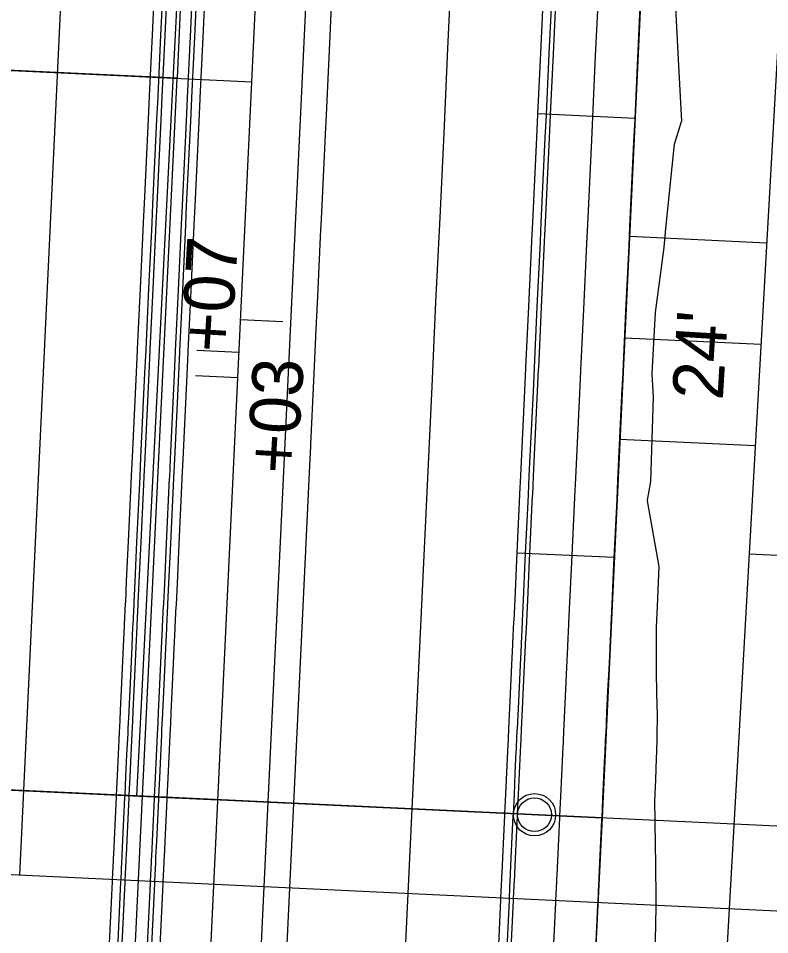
# Model space of a CAD drawing. Extents: x -70 to 701944, y -4 to 666871.
# Drawn here: x 668271.1 to 668360, y 655078.2 to 655186.6 of the extents above; entities that cross this region are included whole.
import ezdxf

# ---------------------------------------------------------------- set-up
doc = ezdxf.new("R2010")
doc.units = 0
for name, color, linetype in [('R_Detour', 7, 'Continuous'), ('R_Drive', 7, 'Continuous'), ('R_Horz Alg', 7, 'Continuous'), ('R_No Plot', 7, 'Continuous'), ('R_Proposed Const Limits', 7, 'Continuous'), ('R_Proposed Road', 7, 'Continuous'), ('R_ROW', 7, 'Continuous'), ('R_ROW Annot', 7, 'Continuous'), ('R_Striping', 7, 'Continuous'), ('R_Water', 7, 'Continuous'), ('T_Indications', 7, 'Continuous')]:
    doc.layers.add(name, color=color, linetype=linetype)

msp = doc.modelspace()

# ---------------------------------------------------------------- linework, layer by layer
at = {"layer": 'R_Detour'}
for p, q in [((668169.67, 655185.14), (668298.7, 655179.05)), ((668151.5, 655100.91), (668294.69, 655094.15)), ((668441.28, 655087.23), (668294.69, 655094.15))]:
    msp.add_line(p, q, dxfattribs=at)
at = {"layer": 'R_Drive'}
for p, q in [((668332.56, 655175.3), (668344.05, 655174.76)), ((668343.39, 655160.78), (668359.61, 655160.01)), ((668297.37, 655150.94), (668302.37, 655150.7)), ((668297.19, 655147.03), (668292.2, 655147.26)), ((668342.26, 655136.8), (668358.27, 655136.05)), ((668330.11, 655123.36), (668341.6, 655122.82))]:
    msp.add_line(p, q, dxfattribs=at)
at = {"layer": 'R_Horz Alg'}
msp.add_line((668254.91, 654251.16), (668327.61, 655791.56), dxfattribs=at)
msp.add_lwpolyline([(668292.06, 655144.33), (668297.05, 655144.09)], dxfattribs=at)
at = {"layer": 'R_No Plot'}
for p, q in [((668342.83, 655148.79), (668358.94, 655148.03)), ((668187.73, 655089.19), (668380.3, 655080.1))]:
    msp.add_line(p, q, dxfattribs=at)
for points in [[(668210.91, 655248.27), (668292.71, 655244.41), (668289.88, 655179.47), (668211.95, 655183.15)], [(668292.71, 655244.41), (668347.22, 655241.84), (668340.15, 655092), (668285.12, 655094.6)], [(668289.88, 655179.47), (668211.95, 655183.15), (668212.78, 655131.9), (668213.03, 655119.43), (668213.82, 655104.92), (668215.37, 655097.89), (668285.78, 655094.57)], [(668285.78, 655094.57), (668215.37, 655097.89), (668216.15, 655093.84), (668225.15, 655058.76), (668230.84, 655034.55), (668233.09, 655014.27), (668233.65, 654985.81), (668233.98, 654965.53), (668233.02, 654946.89), (668287.62, 654944.31), (668288.46, 654962.05), (668284.23, 655062.51)], [(668285.78, 655094.57), (668340.15, 655092), (668338.43, 655057.09), (668331.32, 654965.1), (668330.89, 654959.61), (668330.08, 654942.31), (668287.62, 654944.31), (668288.43, 654961.32), (668284.23, 655062.51)]]:
    msp.add_lwpolyline(points, close=True, dxfattribs=at)
msp.add_circle((668332.16, 655092.38), 2.5, dxfattribs=at)
at = {"layer": 'R_Proposed Const Limits'}
msp.add_lwpolyline([(668346.37, 655071.69), (668346.57, 655081.45), (668346.57, 655081.69), (668346.54, 655083.94), (668346.54, 655084.26), (668346.53, 655084.63), (668346.51, 655086.44), (668346.47, 655088.95), (668346.44, 655091.47), (668346.44, 655091.71), (668346.41, 655093.99), (668346.52, 655096.52), (668346.6, 655099.06), (668346.6, 655099.27), (668346.62, 655099.64), (668346.68, 655101.61), (668346.68, 655101.71), (668346.69, 655104.17), (668346.63, 655106.73), (668346.58, 655109.31), (668346.59, 655111.72), (668346.59, 655111.88), (668346.6, 655114.38), (668346.6, 655114.46), (668346.6, 655114.55), (668346.69, 655117.03), (668346.91, 655121.72), (668345.51, 655129.5), (668345.53, 655129.57), (668345.93, 655131.77), (668346.22, 655141.77), (668346.09, 655144.48), (668346.08, 655144.56), (668346.49, 655151.77), (668347.5, 655159.44), (668347.5, 655159.5), (668347.68, 655161.72), (668348.71, 655171.69), (668349.56, 655174.37), (668349.57, 655174.41), (668349.21, 655181.68), (668348.79, 655189.43)], dxfattribs=at)
at = {"layer": 'R_Proposed Road'}
for points in [[(668281.77, 655074.74), (668282.23, 655084.49), (668282.24, 655084.72), (668282.34, 655086.97), (668282.36, 655087.29), (668282.38, 655087.66), (668282.46, 655089.46), (668282.58, 655091.96), (668282.7, 655094.47), (668282.71, 655094.71), (668282.82, 655097), (668282.94, 655099.53), (668283.06, 655102.06), (668283.07, 655102.27), (668283.08, 655102.64), (668283.18, 655104.61), (668283.18, 655104.7), (668283.3, 655107.16), (668283.42, 655109.72), (668283.54, 655112.28), (668283.65, 655114.69), (668283.66, 655114.85), (668283.78, 655117.35), (668283.78, 655117.42), (668283.79, 655117.52), (668283.9, 655120), (668284.12, 655124.68), (668284.49, 655132.38), (668284.49, 655132.45), (668284.6, 655134.67), (668285.07, 655144.66), (668285.19, 655147.36), (668285.2, 655147.43), (668285.54, 655154.65), (668285.9, 655162.35), (668285.9, 655162.4), (668286.01, 655164.64), (668286.48, 655174.62), (668286.61, 655177.34), (668286.61, 655177.38), (668286.95, 655184.61), (668287.32, 655192.33)], [(668282.77, 655074.69), (668283.23, 655084.44), (668283.24, 655084.68), (668283.34, 655086.92), (668283.36, 655087.24), (668283.38, 655087.61), (668283.46, 655089.41), (668283.58, 655091.91), (668283.7, 655094.43), (668283.71, 655094.67), (668283.82, 655096.95), (668283.94, 655099.48), (668284.06, 655102.02), (668284.07, 655102.22), (668284.08, 655102.59), (668284.18, 655104.56), (668284.18, 655104.66), (668284.3, 655107.11), (668284.42, 655109.67), (668284.54, 655112.23), (668284.65, 655114.64), (668284.66, 655114.8), (668284.78, 655117.3), (668284.78, 655117.37), (668284.79, 655117.47), (668284.9, 655119.95), (668285.12, 655124.63), (668285.49, 655132.33), (668285.49, 655132.4), (668285.59, 655134.62), (668286.07, 655144.61), (668286.19, 655147.31), (668286.2, 655147.39), (668286.54, 655154.6), (668286.9, 655162.3), (668286.9, 655162.36), (668287.01, 655164.59), (668287.48, 655174.58), (668287.61, 655177.29), (668287.61, 655177.34), (668287.95, 655184.57), (668288.32, 655192.29)], [(668283.27, 655074.67), (668283.73, 655084.42), (668283.74, 655084.65), (668283.84, 655086.9), (668283.86, 655087.22), (668283.88, 655087.59), (668283.96, 655089.39), (668284.08, 655091.89), (668284.2, 655094.4), (668284.21, 655094.64), (668284.32, 655096.92), (668284.44, 655099.45), (668284.56, 655101.99), (668284.57, 655102.2), (668284.58, 655102.57), (668284.68, 655104.54), (668284.68, 655104.63), (668284.8, 655107.09), (668284.92, 655109.65), (668285.04, 655112.21), (668285.15, 655114.62), (668285.16, 655114.78), (668285.28, 655117.28), (668285.28, 655117.35), (668285.28, 655117.45), (668285.4, 655119.93), (668285.62, 655124.61), (668285.99, 655132.31), (668285.99, 655132.38), (668286.09, 655134.6), (668286.57, 655144.59), (668286.69, 655147.29), (668286.7, 655147.36), (668287.04, 655154.58), (668287.4, 655162.28), (668287.4, 655162.33), (668287.51, 655164.56), (668287.98, 655174.55), (668288.11, 655177.27), (668288.11, 655177.31), (668288.45, 655184.54), (668288.82, 655192.26)], [(668286.26, 655074.52), (668286.72, 655084.28), (668286.73, 655084.51), (668286.84, 655086.76), (668286.85, 655087.08), (668286.87, 655087.44), (668286.96, 655089.25), (668287.08, 655091.75), (668287.19, 655094.26), (668287.21, 655094.5), (668287.31, 655096.78), (668287.43, 655099.31), (668287.55, 655101.85), (668287.56, 655102.06), (668287.58, 655102.43), (668287.67, 655104.4), (668287.68, 655104.49), (668287.79, 655106.95), (668287.91, 655109.51), (668288.03, 655112.07), (668288.15, 655114.48), (668288.16, 655114.64), (668288.27, 655117.14), (668288.28, 655117.21), (668288.28, 655117.31), (668288.4, 655119.78), (668288.62, 655124.47), (668288.98, 655132.16), (668288.99, 655132.24), (668289.09, 655134.46), (668289.56, 655144.45), (668289.69, 655147.15), (668289.69, 655147.22), (668290.03, 655154.43), (668290.4, 655162.14), (668290.4, 655162.19), (668290.51, 655164.42), (668290.98, 655174.41), (668291.1, 655177.12), (668291.11, 655177.17), (668291.45, 655184.4), (668291.81, 655192.12)], [(668286.76, 655074.5), (668287.22, 655084.25), (668287.23, 655084.49), (668287.34, 655086.73), (668287.35, 655087.05), (668287.37, 655087.42), (668287.46, 655089.22), (668287.57, 655091.73), (668287.69, 655094.24), (668287.7, 655094.48), (668287.81, 655096.76), (668287.93, 655099.29), (668288.05, 655101.83), (668288.06, 655102.04), (668288.08, 655102.4), (668288.17, 655104.37), (668288.18, 655104.47), (668288.29, 655106.92), (668288.41, 655109.48), (668288.53, 655112.05), (668288.65, 655114.46), (668288.65, 655114.61), (668288.77, 655117.11), (668288.78, 655117.19), (668288.78, 655117.28), (668288.9, 655119.76), (668289.12, 655124.44), (668289.48, 655132.14), (668289.49, 655132.22), (668289.59, 655134.43), (668290.06, 655144.42), (668290.19, 655147.12), (668290.19, 655147.2), (668290.53, 655154.41), (668290.9, 655162.11), (668290.9, 655162.17), (668291, 655164.4), (668291.48, 655174.39), (668291.6, 655177.1), (668291.61, 655177.15), (668291.95, 655184.38), (668292.31, 655192.1)], [(668287.76, 655074.45), (668288.22, 655084.21), (668288.23, 655084.44), (668288.34, 655086.69), (668288.35, 655087.01), (668288.37, 655087.37), (668288.46, 655089.18), (668288.57, 655091.68), (668288.69, 655094.19), (668288.7, 655094.43), (668288.81, 655096.71), (668288.93, 655099.24), (668289.05, 655101.78), (668289.06, 655101.99), (668289.08, 655102.36), (668289.17, 655104.33), (668289.17, 655104.42), (668289.29, 655106.88), (668289.41, 655109.44), (668289.53, 655112), (668289.65, 655114.41), (668289.65, 655114.57), (668289.77, 655117.06), (668289.78, 655117.14), (668289.78, 655117.24), (668289.9, 655119.71), (668290.12, 655124.4), (668290.48, 655132.09), (668290.48, 655132.17), (668290.59, 655134.39), (668291.06, 655144.38), (668291.19, 655147.08), (668291.19, 655147.15), (668291.53, 655154.36), (668291.9, 655162.06), (668291.9, 655162.12), (668292, 655164.35), (668292.47, 655174.34), (668292.6, 655177.05), (668292.61, 655177.1), (668292.95, 655184.33), (668293.31, 655192.05)], [(668327.72, 655072.57), (668328.18, 655082.32), (668328.19, 655082.56), (668328.29, 655084.8), (668328.31, 655085.12), (668328.33, 655085.49), (668328.41, 655087.29), (668328.53, 655089.79), (668328.65, 655092.31), (668328.66, 655092.54), (668328.77, 655094.83), (668328.89, 655097.36), (668329.01, 655099.89), (668329.02, 655100.1), (668329.03, 655100.47), (668329.13, 655102.44), (668329.13, 655102.53), (668329.25, 655104.99), (668329.37, 655107.55), (668329.49, 655110.11), (668329.6, 655112.52), (668329.61, 655112.68), (668329.73, 655115.18), (668329.73, 655115.25), (668329.74, 655115.35), (668329.85, 655117.83), (668330.07, 655122.51), (668330.44, 655130.21), (668330.44, 655130.28), (668330.54, 655132.5), (668331.02, 655142.49), (668331.14, 655145.19), (668331.15, 655145.27), (668331.49, 655152.48), (668331.85, 655160.18), (668331.85, 655160.24), (668331.96, 655162.47), (668332.43, 655172.46), (668332.56, 655175.17), (668332.56, 655175.21), (668332.9, 655182.44), (668333.27, 655190.16)], [(668328.71, 655072.52), (668329.18, 655082.27), (668329.19, 655082.51), (668329.29, 655084.75), (668329.31, 655085.07), (668329.32, 655085.44), (668329.41, 655087.24), (668329.53, 655089.75), (668329.65, 655092.26), (668329.66, 655092.5), (668329.77, 655094.78), (668329.88, 655097.31), (668330, 655099.85), (668330.01, 655100.06), (668330.03, 655100.42), (668330.12, 655102.39), (668330.13, 655102.49), (668330.25, 655104.94), (668330.37, 655107.5), (668330.49, 655110.07), (668330.6, 655112.48), (668330.61, 655112.63), (668330.73, 655115.13), (668330.73, 655115.21), (668330.73, 655115.3), (668330.85, 655117.78), (668331.07, 655122.46), (668331.44, 655130.16), (668331.44, 655130.24), (668331.54, 655132.45), (668332.02, 655142.44), (668332.14, 655145.14), (668332.15, 655145.22), (668332.49, 655152.43), (668332.85, 655160.13), (668332.85, 655160.19), (668332.96, 655162.42), (668333.43, 655172.41), (668333.56, 655175.12), (668333.56, 655175.17), (668333.9, 655182.4), (668334.27, 655190.12)], [(668329.21, 655072.5), (668329.67, 655082.25), (668329.69, 655082.49), (668329.79, 655084.73), (668329.81, 655085.05), (668329.82, 655085.42), (668329.91, 655087.22), (668330.03, 655089.72), (668330.15, 655092.23), (668330.16, 655092.47), (668330.26, 655094.76), (668330.38, 655097.29), (668330.5, 655099.82), (668330.51, 655100.03), (668330.53, 655100.4), (668330.62, 655102.37), (668330.63, 655102.46), (668330.74, 655104.92), (668330.87, 655107.48), (668330.99, 655110.04), (668331.1, 655112.45), (668331.11, 655112.61), (668331.23, 655115.11), (668331.23, 655115.18), (668331.23, 655115.28), (668331.35, 655117.76), (668331.57, 655122.44), (668331.93, 655130.14), (668331.94, 655130.21), (668332.04, 655132.43), (668332.51, 655142.42), (668332.64, 655145.12), (668332.65, 655145.19), (668332.99, 655152.41), (668333.35, 655160.11), (668333.35, 655160.17), (668333.46, 655162.4), (668333.93, 655172.39), (668334.06, 655175.1), (668334.06, 655175.14), (668334.4, 655182.37), (668334.76, 655190.09)], [(668334.21, 655072.26), (668334.67, 655082.01), (668334.68, 655082.25), (668334.79, 655084.49), (668334.8, 655084.81), (668334.82, 655085.18), (668334.9, 655086.98), (668335.02, 655089.49), (668335.14, 655092), (668335.15, 655092.24), (668335.26, 655094.52), (668335.38, 655097.05), (668335.5, 655099.59), (668335.51, 655099.8), (668335.53, 655100.17), (668335.62, 655102.13), (668335.62, 655102.23), (668335.74, 655104.69), (668335.86, 655107.24), (668335.98, 655109.81), (668336.09, 655112.22), (668336.1, 655112.37), (668336.22, 655114.87), (668336.22, 655114.95), (668336.23, 655115.04), (668336.34, 655117.52), (668336.57, 655122.21), (668336.93, 655129.9), (668336.93, 655129.98), (668337.04, 655132.19), (668337.51, 655142.18), (668337.64, 655144.88), (668337.64, 655144.96), (668337.98, 655152.17), (668338.34, 655159.87), (668338.35, 655159.93), (668338.45, 655162.16), (668338.92, 655172.15), (668339.05, 655174.86), (668339.05, 655174.91), (668339.39, 655182.14), (668339.76, 655189.86)], [(668339.2, 655072.02), (668339.66, 655081.78), (668339.67, 655082.01), (668339.78, 655084.26), (668339.8, 655084.58), (668339.81, 655084.95), (668339.9, 655086.75), (668340.02, 655089.25), (668340.13, 655091.76), (668340.15, 655092), (668340.25, 655094.28), (668340.37, 655096.81), (668340.49, 655099.35), (668340.5, 655099.56), (668340.52, 655099.93), (668340.61, 655101.9), (668340.62, 655101.99), (668340.73, 655104.45), (668340.85, 655107.01), (668340.98, 655109.57), (668341.09, 655111.98), (668341.1, 655112.14), (668341.21, 655114.64), (668341.22, 655114.71), (668341.22, 655114.81), (668341.34, 655117.29), (668341.56, 655121.97), (668341.92, 655129.67), (668341.93, 655129.74), (668342.03, 655131.96), (668342.5, 655141.95), (668342.63, 655144.65), (668342.63, 655144.72), (668342.97, 655151.94), (668343.34, 655159.64), (668343.34, 655159.69), (668343.45, 655161.92), (668343.92, 655171.91), (668344.05, 655174.63), (668344.05, 655174.67), (668344.39, 655181.9), (668344.75, 655189.62)]]:
    msp.add_lwpolyline(points, dxfattribs=at)
at = {"layer": 'R_ROW'}
msp.add_lwpolyline([(668379.35, 655858.1), (668375.98, 655777.07), (668370.36, 655679.23), (668386.89, 655520.28), (668407.12, 655376.16), (668401.28, 655337.39), (668367.53, 655300.94), (668336.13, 654741.8), (668319.02, 654252.06), (668346.25, 654066.79), (668364.92, 653986.53), (668401.01, 653983.18), (668425.78, 653872.16), (668398.63, 653868.03), (668433.79, 653730.98), (668450.99, 653639.16), (668466.96, 653535.35), (668502.13, 653505.82)], dxfattribs=at)
at = {"layer": 'R_ROW Annot'}
msp.add_lwpolyline([(668357.55, 655123.22), (668392.51, 655121.57)], dxfattribs=at)
at = {"layer": 'R_Striping'}
msp.add_line((668271.25, 655085.25), (668286.33, 655404.86), dxfattribs=at)
for points in [[(668299.16, 655062.11), (668299.24, 655063.89), (668299.71, 655073.88), (668300.18, 655083.87), (668300.66, 655093.86), (668301.13, 655103.84), (668301.6, 655113.83), (668302.07, 655123.82), (668302.54, 655133.81), (668303.01, 655143.8), (668303.48, 655153.79), (668303.96, 655163.78), (668304.43, 655173.77), (668304.9, 655183.75), (668305.37, 655193.74), (668305.84, 655203.73), (668306.31, 655213.72), (668306.78, 655223.71), (668307.26, 655233.7), (668307.73, 655243.69), (668308.69, 655264.01)], [(668310.96, 654993.6), (668311.74, 655003.58), (668312.51, 655013.55), (668313.07, 655020.85), (668313.28, 655023.53), (668314.05, 655033.5), (668314.82, 655043.48), (668315.59, 655053.45), (668316.14, 655060.59), (668316.26, 655063.1), (668316.73, 655073.09), (668317.2, 655083.08), (668317.68, 655093.07), (668318.15, 655103.06), (668318.62, 655113.04), (668319.09, 655123.03), (668319.56, 655133.02), (668320.03, 655143.01), (668320.5, 655153), (668320.98, 655162.99), (668321.45, 655172.98), (668321.92, 655182.97), (668322.39, 655192.96)]]:
    msp.add_lwpolyline(points, dxfattribs=at)
at = {"layer": 'R_Water'}
msp.add_circle((668332.16, 655092.38), 2, dxfattribs=at)
at = {"layer": 'T_Indications'}
msp.add_lwpolyline([(668302.78, 655074.6), (668303.21, 655083.73), (668303.68, 655093.72), (668303.92, 655098.72), (668303.93, 655098.87), (668304.16, 655103.71), (668304.63, 655113.7), (668305.06, 655122.85), (668305.09, 655123.51), (668305.1, 655123.69), (668305.57, 655133.68), (668305.68, 655135.92), (668305.69, 655136.2), (668306.04, 655143.67), (668306.29, 655148.9), (668306.29, 655149), (668306.51, 655153.66), (668306.89, 655161.6), (668306.91, 655162.08), (668306.98, 655163.65), (668307.46, 655173.63), (668307.49, 655174.29), (668307.53, 655175.16), (668307.93, 655183.62), (668308.14, 655188.05)], dxfattribs=at)

# ---------------------------------------------------------------- texts
at = {"layer": 'R_Drive'}
for s, p in [('+07', (668296.27, 655146.94)), ("24'", (668354.43, 655141.32)), ('+03', (668304.06, 655132.58))]:
    msp.add_text(s, height=6, rotation=86.5585, dxfattribs=at).set_placement(p)
at = {"layer": 'R_No Plot'}
for p in [(668297.43, 655151.04), (668297.24, 655147.04)]:
    msp.add_text('+', height=0.1, rotation=87.2978, dxfattribs=at).set_placement(p)

doc.saveas('drawing.dxf')
